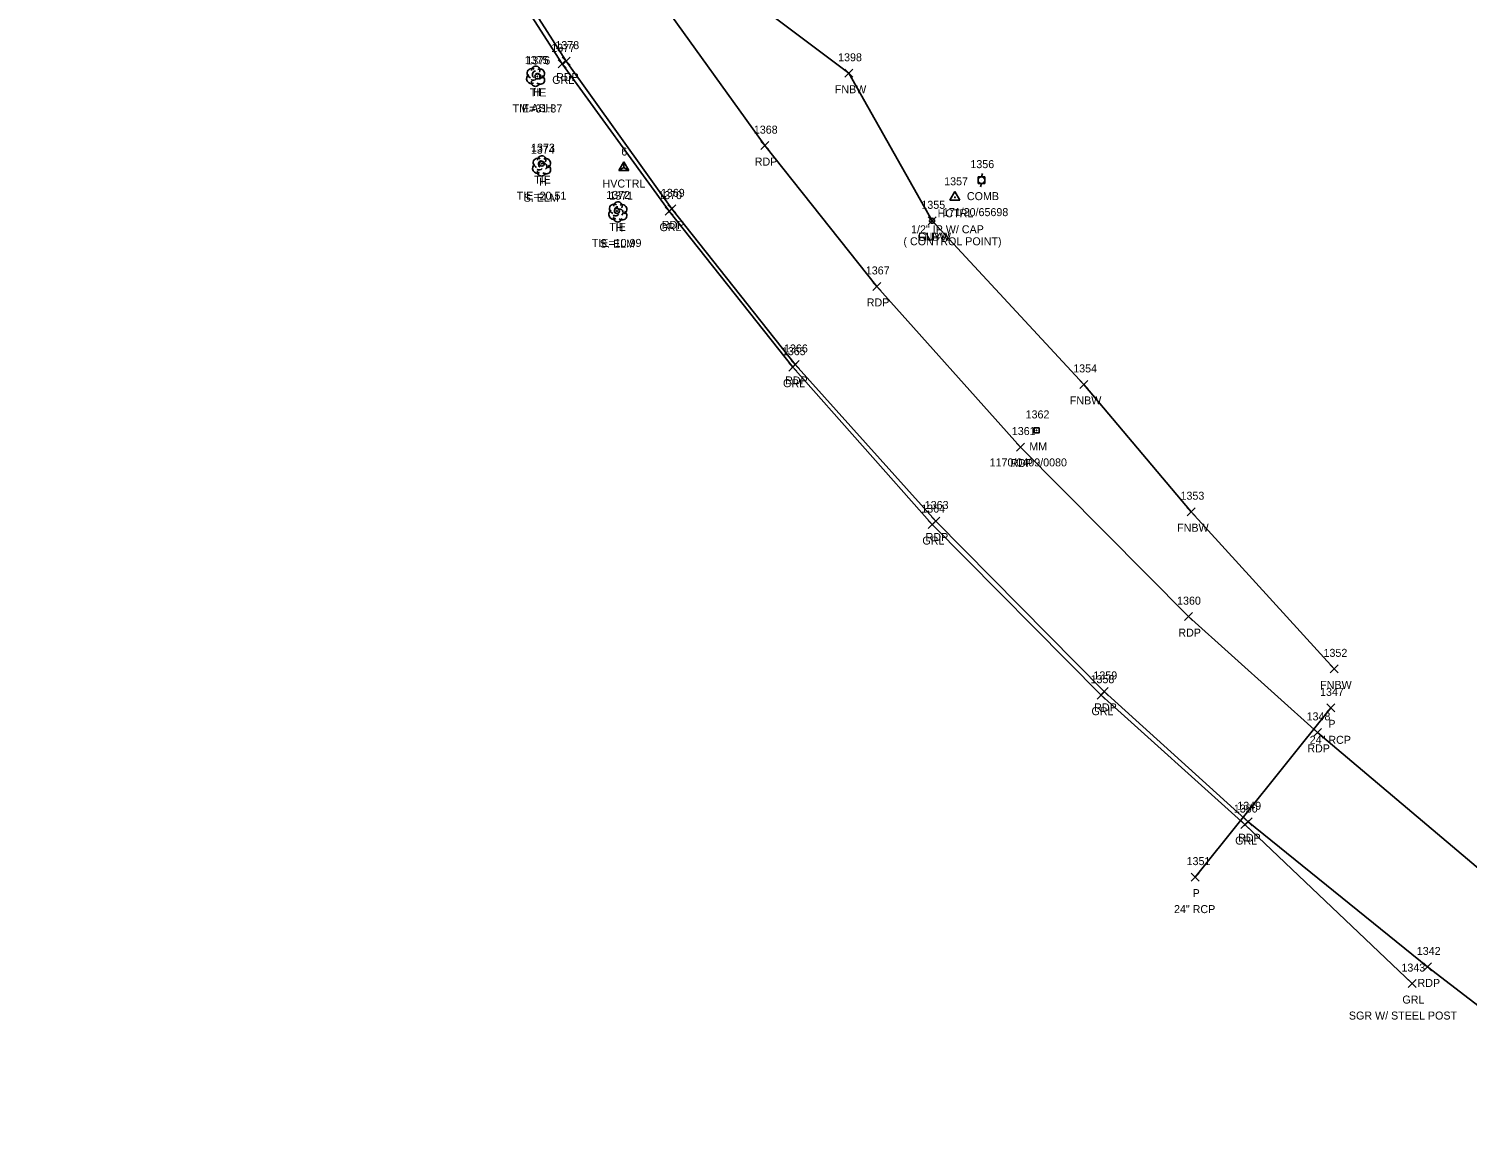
# Model space of a CAD drawing. Extents: x 1503463 to 1505240, y 712171 to 717196.
# Drawn here: x 1503601.7 to 1503961.3, y 715346.9 to 715621.6 of the extents above; entities that cross this region are included whole.
import ezdxf

# ---------------------------------------------------------------- set-up
doc = ezdxf.new("R2010")
doc.units = 0
for name, color, linetype in [('C_A', 7, 'Continuous'), ('C_C', 7, 'Continuous'), ('C_I', 7, 'Continuous'), ('CBP', 7, 'Continuous'), ('CPH', 7, 'Continuous'), ('CPSM', 7, 'Continuous'), ('D_A', 7, 'Continuous'), ('D_C', 7, 'Continuous'), ('D_I', 7, 'Continuous'), ('D_TIC', 7, 'Continuous'), ('DCP', 7, 'Continuous'), ('L_A', 7, 'Continuous'), ('L_C', 7, 'Continuous'), ('L_I', 7, 'Continuous'), ('L_TIC', 7, 'Continuous'), ('LFNC', 7, 'Continuous'), ('LTD', 7, 'Continuous'), ('P_A', 7, 'Continuous'), ('P_I', 7, 'Continuous'), ('P_TIC', 7, 'Continuous'), ('PET', 7, 'Continuous'), ('R_A', 7, 'Continuous'), ('R_C', 7, 'Continuous'), ('R_I', 7, 'Continuous'), ('R_TIC', 7, 'Continuous'), ('RGR', 7, 'Continuous'), ('S_A', 7, 'Continuous'), ('S_C', 7, 'Continuous'), ('S_I', 7, 'Continuous'), ('SRM', 7, 'Continuous'), ('U_A', 7, 'Continuous'), ('U_C', 7, 'Continuous'), ('U_I', 7, 'Continuous'), ('UP', 7, 'Continuous'), ('UPGW', 7, 'Continuous')]:
    doc.layers.add(name, color=color, linetype=linetype)

msp = doc.modelspace()

# ---------------------------------------------------------------- linework, layer by layer
at = {"layer": 'CBP'}
for centre, radius in [((1503728.87, 715609.69), 0.625), ((1503728.87, 715609.69), 0.0833), ((1503729.97, 715587.89), 0.625), ((1503729.97, 715587.89), 0.0833), ((1503748.75, 715576.07), 0.625), ((1503748.75, 715576.07), 0.0833)]:
    msp.add_circle(centre, radius, dxfattribs=at)
at = {"layer": 'CPH'}
for p, q in [((1503831.98, 715578.76), (1503833.23, 715580.93)), ((1503831.98, 715578.76), (1503834.48, 715578.76)), ((1503834.48, 715578.76), (1503833.23, 715580.93)), ((1503833.23, 715579.48), (1503833.23, 715579.48))]:
    msp.add_line(p, q, dxfattribs=at)
msp.add_circle((1503833.23, 715579.48), 0.0833, dxfattribs=at)
at = {"layer": 'CPSM'}
for p, q in [((1503749.21, 715586.2), (1503750.46, 715588.37)), ((1503749.21, 715586.2), (1503750.46, 715586.92)), ((1503749.21, 715586.2), (1503751.71, 715586.2)), ((1503751.71, 715586.2), (1503750.46, 715588.37)), ((1503750.46, 715586.92), (1503750.46, 715588.37)), ((1503750.46, 715586.92), (1503750.46, 715586.92)), ((1503750.46, 715586.92), (1503751.71, 715586.2))]:
    msp.add_line(p, q, dxfattribs=at)
at = {"layer": 'D_TIC'}
for points in [[(1503926.18, 715450.82), (1503928.18, 715452.82)], [(1503928.18, 715450.82), (1503926.18, 715452.82)], [(1503892.26, 715408.49), (1503894.26, 715410.49)], [(1503894.26, 715408.49), (1503892.26, 715410.49)]]:
    msp.add_lwpolyline(points, dxfattribs=at)
at = {"layer": 'DCP'}
msp.add_lwpolyline([(1503927.18, 715451.82), (1503893.26, 715409.49)], dxfattribs=at)
at = {"layer": 'L_TIC'}
for points in [[(1503805.72, 715609.49), (1503807.72, 715611.49)], [(1503807.72, 715609.49), (1503805.72, 715611.49)], [(1503826.53, 715572.6), (1503828.53, 715574.6)], [(1503828.53, 715572.6), (1503826.53, 715574.6)], [(1503864.48, 715531.69), (1503866.48, 715533.69)], [(1503866.48, 715531.69), (1503864.48, 715533.69)], [(1503891.3, 715499.86), (1503893.3, 715501.86)], [(1503893.3, 715499.86), (1503891.3, 715501.86)], [(1503927.04, 715460.57), (1503929.04, 715462.57)], [(1503929.04, 715460.57), (1503927.04, 715462.57)]]:
    msp.add_lwpolyline(points, dxfattribs=at)
at = {"layer": 'LFNC'}
msp.add_lwpolyline([(1503928.04, 715461.57), (1503892.3, 715500.86), (1503865.48, 715532.69), (1503827.53, 715573.6), (1503806.72, 715610.49), (1503767.01, 715640.34), (1503749.33, 715668.81), (1503734.34, 715687.63), (1503710.07, 715734.45), (1503688.07, 715773.01), (1503683.38, 715803.43), (1503670.55, 715835.21), (1503661.34, 715848.63), (1503646.28, 715894.79)], dxfattribs=at)
at = {"layer": 'LTD'}
for p, q in [((1503728.39, 715609.8), (1503728.39, 715609.8)), ((1503728.39, 715609.8), (1503728.39, 715609.8)), ((1503729.9, 715587.38), (1503729.9, 715587.38)), ((1503729.9, 715587.38), (1503729.9, 715587.38)), ((1503748.94, 715575.89), (1503748.94, 715575.89)), ((1503748.94, 715575.89), (1503748.94, 715575.89))]:
    msp.add_line(p, q, dxfattribs=at)
for centre in [(1503728.44, 715611.24), (1503729.95, 715588.82), (1503748.98, 715577.32)]:
    msp.add_arc(centre, 1.05, 335.5272, 180.9563, dxfattribs=at)
for centre, major_axis, ratio, start_param, end_param in [((1503727.6, 715610.47), (1.21, -0.51), 0.895232, 1.570796, 4.712389), ((1503728.18, 715610.26), (-0.208, -0.792), 0.645439, 3.141593, 6.283185), ((1503729.43, 715610.38), (-1.14, -0.48), 0.949671, 1.570796, 4.712389), ((1503727.31, 715609.09), (0.58, -1.04), 0.959034, 3.141593, 6.283185), ((1503728.39, 715608.3), (0.26, 1.06), 0.942809, 1.570796, 4.712389), ((1503727.93, 715609.05), (-0.625, -0.083), 0.423636, 0, 3.141593), ((1503728.89, 715609.63), (-0.5, 0.667), 0.989748, 3.141593, 6.283185), ((1503729.39, 715608.97), (-1.09, 0.79), 0.841452, 1.570796, 4.712389), ((1503729.11, 715588.05), (1.21, -0.51), 0.895232, 1.570796, 4.712389), ((1503730.94, 715587.97), (-1.14, -0.48), 0.949671, 1.570796, 4.712389), ((1503728.82, 715586.68), (0.58, -1.04), 0.959034, 3.141593, 6.283185), ((1503729.9, 715585.88), (0.26, 1.06), 0.942809, 1.570796, 4.712389), ((1503729.44, 715586.63), (-0.625, -0.083), 0.423636, 0, 3.141593), ((1503729.69, 715587.84), (-0.208, -0.792), 0.645439, 3.141593, 6.283185), ((1503730.4, 715587.22), (-0.5, 0.667), 0.989748, 3.141593, 6.283185), ((1503730.9, 715586.55), (-1.09, 0.79), 0.841452, 1.570796, 4.712389), ((1503747.85, 715575.18), (0.58, -1.04), 0.959034, 3.141593, 6.283185), ((1503748.14, 715576.55), (1.21, -0.51), 0.895232, 1.570796, 4.712389), ((1503748.48, 715575.14), (-0.625, -0.083), 0.423636, 0, 3.141593), ((1503748.73, 715576.34), (-0.208, -0.792), 0.645439, 3.141593, 6.283185), ((1503749.44, 715575.72), (-0.5, 0.667), 0.989748, 3.141593, 6.283185), ((1503749.94, 715575.05), (-1.09, 0.79), 0.841452, 1.570796, 4.712389), ((1503749.98, 715576.47), (-1.14, -0.48), 0.949671, 1.570796, 4.712389), ((1503748.94, 715574.39), (0.26, 1.06), 0.942809, 1.570796, 4.712389)]:
    msp.add_ellipse(centre, major_axis=major_axis, ratio=ratio, start_param=start_param, end_param=end_param, dxfattribs=at)
at = {"layer": 'P_TIC'}
for points in [[(1503735.04, 715612.53), (1503737.04, 715614.53)], [(1503737.04, 715612.53), (1503735.04, 715614.53)], [(1503784.7, 715591.4), (1503786.7, 715593.4)], [(1503786.7, 715591.4), (1503784.7, 715593.4)], [(1503761.47, 715575.59), (1503763.47, 715577.59)], [(1503763.47, 715575.59), (1503761.47, 715577.59)], [(1503812.69, 715556.19), (1503814.69, 715558.19)], [(1503814.69, 715556.19), (1503812.69, 715558.19)], [(1503792.3, 715536.68), (1503794.3, 715538.68)], [(1503794.3, 715536.68), (1503792.3, 715538.68)], [(1503848.62, 715516.03), (1503850.62, 715518.03)], [(1503850.62, 715516.03), (1503848.62, 715518.03)], [(1503827.42, 715497.53), (1503829.42, 715499.53)], [(1503829.42, 715497.53), (1503827.42, 715499.53)], [(1503890.58, 715473.62), (1503892.58, 715475.62)], [(1503892.58, 715473.62), (1503890.58, 715475.62)], [(1503869.54, 715454.93), (1503871.54, 715456.93)], [(1503871.54, 715454.93), (1503869.54, 715456.93)], [(1503922.82, 715444.68), (1503924.82, 715446.68)], [(1503924.82, 715444.68), (1503922.82, 715446.68)], [(1503905.51, 715422.33), (1503907.51, 715424.33)], [(1503907.51, 715422.33), (1503905.51, 715424.33)], [(1503950.37, 715386.03), (1503952.37, 715388.03)], [(1503952.37, 715386.03), (1503950.37, 715388.03)]]:
    msp.add_lwpolyline(points, dxfattribs=at)
at = {"layer": 'PET'}
for points in [[(1504086.6, 715320.97), (1504048.23, 715348.08), (1504021.82, 715368.03), (1503966.17, 715409.92), (1503923.82, 715445.68), (1503891.58, 715474.62), (1503849.62, 715517.03), (1503813.69, 715557.19), (1503785.7, 715592.4), (1503758.96, 715629.69), (1503731.53, 715672.92), (1503706.38, 715717.5), (1503684.24, 715763.13), (1503664.14, 715810.3), (1503646.76, 715858.44), (1503630.24, 715911.59)], [(1504010.26, 715341.79), (1503951.37, 715387.03), (1503906.51, 715423.33), (1503870.54, 715455.93), (1503828.42, 715498.53), (1503793.3, 715537.68), (1503762.47, 715576.59), (1503736.04, 715613.53), (1503707.39, 715658.39), (1503681.7, 715703.45), (1503658.24, 715752.13), (1503638.35, 715798.92), (1503620.07, 715849.48), (1503602.71, 715905.3)]]:
    msp.add_lwpolyline(points, dxfattribs=at)
at = {"layer": 'R_TIC'}
for points in [[(1503734.02, 715611.85), (1503736.02, 715613.85)], [(1503736.02, 715611.85), (1503734.02, 715613.85)], [(1503760.83, 715575.02), (1503762.83, 715577.02)], [(1503762.83, 715575.02), (1503760.83, 715577.02)], [(1503791.71, 715536), (1503793.71, 715538)], [(1503793.71, 715536), (1503791.71, 715538)], [(1503826.55, 715496.64), (1503828.55, 715498.64)], [(1503828.55, 715496.64), (1503826.55, 715498.64)], [(1503868.81, 715453.98), (1503870.81, 715455.98)], [(1503870.81, 715453.98), (1503868.81, 715455.98)], [(1503904.72, 715421.63), (1503906.72, 715423.63)], [(1503906.72, 715421.63), (1503904.72, 715423.63)], [(1503946.53, 715381.87), (1503948.53, 715383.87)], [(1503948.53, 715381.87), (1503946.53, 715383.87)]]:
    msp.add_lwpolyline(points, dxfattribs=at)
at = {"layer": 'RGR'}
msp.add_lwpolyline([(1503947.53, 715382.87), (1503905.72, 715422.63), (1503869.81, 715454.98), (1503827.55, 715497.64), (1503792.71, 715537), (1503761.83, 715576.02), (1503735.02, 715612.85), (1503706.21, 715657.74), (1503680.6, 715703.16), (1503657.03, 715751.97), (1503637.42, 715798.81), (1503619.03, 715849.2), (1503601.73, 715905.18)], dxfattribs=at)
at = {"layer": 'SRM'}
msp.add_lwpolyline([(1503853, 715521.81), (1503854.25, 715521.81), (1503854.25, 715520.56), (1503853, 715520.56)], close=True, dxfattribs=at)
msp.add_circle((1503853.63, 715521.19), 0.0833, dxfattribs=at)
at = {"layer": 'UP'}
for p, q in [((1503839, 715582.94), (1503839, 715584.6)), ((1503839, 715584.6), (1503840.67, 715584.6)), ((1503840.67, 715582.94), (1503839, 715582.94)), ((1503839.59, 715582.1), (1503839.84, 715582.94)), ((1503840.09, 715585.44), (1503839.84, 715584.6)), ((1503839.84, 715583.77), (1503839.84, 715583.77)), ((1503840.67, 715584.6), (1503840.67, 715582.94))]:
    msp.add_line(p, q, dxfattribs=at)
msp.add_circle((1503839.84, 715583.77), 0.833, dxfattribs=at)
at = {"layer": 'UPGW'}
for radius in [0.625, 0.0833]:
    msp.add_circle((1503827.53, 715573.6), radius, dxfattribs=at)

# ---------------------------------------------------------------- texts
at = {"layer": 'C_A'}
for s, p in [('TIE', (1503726.95, 715604.69)), ('TIE', (1503728.05, 715582.89)), ('HVCTRL', (1503745.15, 715581.92)), ('HCTRL', (1503828.9, 715574.48)), ('TIE', (1503746.83, 715571.07))]:
    msp.add_text(s, height=2, dxfattribs=at).set_placement(p)
at = {"layer": 'C_C'}
for s, p in [('TIE=31.37', (1503722.66, 715600.69)), ('TIE=20.51', (1503723.69, 715578.89)), ('1/2" IP W/ CAP', (1503822.26, 715570.48)), ('TIE=10.99', (1503742.46, 715567.07)), ('( CONTROL POINT)', (1503820.36, 715567.48))]:
    msp.add_text(s, height=2, dxfattribs=at).set_placement(p)
at = {"layer": 'C_I'}
for s, p in [('1376', (1503726.12, 715612.69)), ('1373', (1503727.28, 715590.89)), ('6', (1503749.84, 715589.92)), ('1357', (1503830.54, 715582.48)), ('1372', (1503746.06, 715579.07))]:
    msp.add_text(s, height=2, dxfattribs=at).set_placement(p)
at = {"layer": 'D_A'}
for p in [(1503926.56, 715446.82), (1503892.64, 715404.49)]:
    msp.add_text('P', height=2, dxfattribs=at).set_placement(p)
at = {"layer": 'D_C'}
for p in [(1503921.9, 715442.82), (1503887.98, 715400.49)]:
    msp.add_text('24" RCP', height=2, dxfattribs=at).set_placement(p)
at = {"layer": 'D_I'}
for s, p in [('1347', (1503924.49, 715454.82)), ('1351', (1503891.13, 715412.49))]:
    msp.add_text(s, height=2, dxfattribs=at).set_placement(p)
at = {"layer": 'L_A'}
for s, p in [('FNBW', (1503803.2, 715605.49)), ('H', (1503727.82, 715604.8)), ('H', (1503729.33, 715582.38)), ('H', (1503748.37, 715570.89)), ('FNBW', (1503824, 715568.6)), ('FNBW', (1503861.95, 715527.69)), ('FNBW', (1503888.77, 715495.86)), ('FNBW', (1503924.52, 715456.57))]:
    msp.add_text(s, height=2, dxfattribs=at).set_placement(p)
at = {"layer": 'L_C'}
for s, p in [('M.ASH', (1503724.34, 715600.8)), ('S. ELM', (1503725.44, 715578.38)), ('S. ELM', (1503744.48, 715566.89))]:
    msp.add_text(s, height=2, dxfattribs=at).set_placement(p)
at = {"layer": 'L_I'}
for s, p in [('1375', (1503725.7, 715612.8)), ('1398', (1503804.03, 715613.49)), ('1374', (1503727.21, 715590.38)), ('1371', (1503746.81, 715578.89)), ('1355', (1503824.84, 715576.6)), ('1354', (1503862.79, 715535.69)), ('1353', (1503889.61, 715503.86)), ('1352', (1503925.35, 715464.57))]:
    msp.add_text(s, height=2, dxfattribs=at).set_placement(p)
at = {"layer": 'P_A'}
for p in [(1503733.53, 715608.53), (1503783.19, 715587.4), (1503759.96, 715571.59), (1503811.18, 715552.19), (1503790.78, 715532.68), (1503847.1, 715512.03), (1503825.9, 715493.53), (1503889.07, 715469.62), (1503868.03, 715450.93), (1503921.3, 715440.68), (1503904, 715418.33), (1503948.85, 715382.03)]:
    msp.add_text('RDP', height=2, dxfattribs=at).set_placement(p)
at = {"layer": 'P_I'}
for s, p in [('1378', (1503733.35, 715616.53)), ('1368', (1503782.96, 715595.4)), ('1369', (1503759.73, 715579.59)), ('1367', (1503810.95, 715560.19)), ('1366', (1503790.5, 715540.68)), ('1361', (1503847.44, 715520.03)), ('1363', (1503825.68, 715501.53)), ('1360', (1503888.75, 715477.62)), ('1359', (1503867.84, 715458.93)), ('1348', (1503921.12, 715448.68)), ('1349', (1503903.81, 715426.33)), ('1342', (1503948.67, 715390.03))]:
    msp.add_text(s, height=2, dxfattribs=at).set_placement(p)
at = {"layer": 'R_A'}
for p in [(1503732.57, 715607.85), (1503759.38, 715571.02), (1503790.25, 715532), (1503825.09, 715492.64), (1503867.35, 715449.98), (1503903.27, 715417.63), (1503945.07, 715377.87)]:
    msp.add_text('GRL', height=2, dxfattribs=at).set_placement(p)
at = {"layer": 'R_C'}
msp.add_text('SGR W/ STEEL POST', height=2, dxfattribs=at).set_placement((1503931.69, 715373.87))
at = {"layer": 'R_I'}
for s, p in [('1377', (1503732.33, 715615.85)), ('1370', (1503759.05, 715579.02)), ('1365', (1503789.97, 715540)), ('1364', (1503824.81, 715500.64)), ('1358', (1503867.12, 715457.98)), ('1350', (1503902.94, 715425.63)), ('1343', (1503944.83, 715385.87))]:
    msp.add_text(s, height=2, dxfattribs=at).set_placement(p)
at = {"layer": 'S_A'}
msp.add_text('MM', height=2, dxfattribs=at).set_placement((1503851.82, 715516.19))
at = {"layer": 'S_C'}
msp.add_text('1170/0409/0080', height=2, dxfattribs=at).set_placement((1503841.89, 715512.19))
at = {"layer": 'S_I'}
msp.add_text('1362', height=2, dxfattribs=at).set_placement((1503850.89, 715524.19))
at = {"layer": 'U_A'}
for s, p in [('COMB', (1503836.22, 715578.77)), ('GUYW', (1503823.92, 715568.6))]:
    msp.add_text(s, height=2, dxfattribs=at).set_placement(p)
at = {"layer": 'U_C'}
msp.add_text('171/20/65698', height=2, dxfattribs=at).set_placement((1503830.2, 715574.77))
at = {"layer": 'U_I'}
for s, p in [('1356', (1503837.09, 715586.77)), ('1355', (1503824.84, 715576.6))]:
    msp.add_text(s, height=2, dxfattribs=at).set_placement(p)

doc.saveas('drawing.dxf')
